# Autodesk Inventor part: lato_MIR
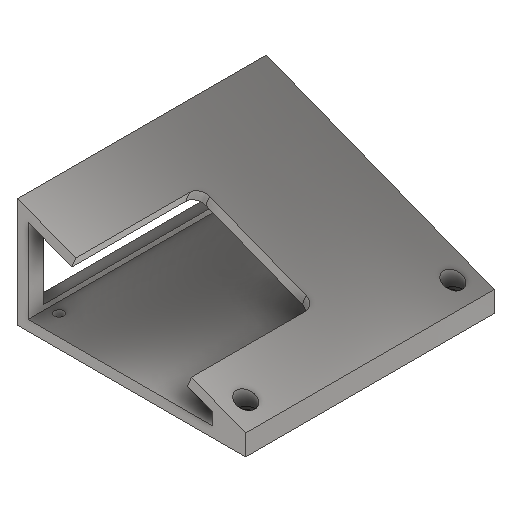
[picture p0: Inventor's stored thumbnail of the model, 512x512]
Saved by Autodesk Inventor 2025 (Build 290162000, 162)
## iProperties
Created: 2025-05
Part Number: lato_MIR
Material: Plastica PET
Document SubType Name: Modeling
Designer: R5800u
Density: 1.541 g/cm^3
Appearance: Policarbonato - Trasparente
Author: R5800u
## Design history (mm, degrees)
derived "lato.ipt"
  sketch "Schizzo1"
    geometry: L1 (0, 0)-(-190, 0) reference; L2 (-190, 0)-(-190, 5) reference; L3 (0, 5)-(-190, 5) reference; L4 (0, 0)-(0, 5) reference; L5 (-300, -48)-(-300, -53) reference; L6 (-300, -48)-(-300, -38) reference; L7 (-300, -38)-(-190, 5) reference; L8 (-190, 5)-(-190, -48) reference; L9 (-190, -48)-(-300, -48) reference; L10 (-195, -2.323)-(-295, -41.414) reference; L11 (-295, -41.414)-(-295, -43) reference; L12 (-295, -43)-(-195, -43) reference; L13 (-195, -43)-(-195, -2.323) reference; L14 (-284, -37.114)-(-284, -43) reference
  sketch "Schizzo2"
    geometry: L1 (0, 53)-(0, 0) reference; L2 (0, 53)-(120, 53) reference; L3 (120, 0)-(120, 53) reference; L4 (0, 0)-(120, 0) reference; L5 (112.5, 45.5)-(7.5, 45.5) reference; L6 (7.5, 45.5)-(7.5, 7.5) reference; L7 (7.5, 7.5)-(112.5, 7.5) reference; L8 (112.5, 7.5)-(112.5, 45.5) reference; 1 further point
  sketch "Schizzo3"
    geometry: L1 (-81.5, -69.5)-(-81.5, -61.5) reference; L2 (-93.5, -69.5)-(-81.5, -69.5) reference; L3 (-93.5, -61.5)-(-93.5, -69.5) reference; L4 (-81.5, -61.5)-(-93.5, -61.5) reference; L5 (-93.5, 61.5)-(-81.5, 61.5) reference; L6 (-81.5, 61.5)-(-81.5, 69.5) reference; L7 (-81.5, 69.5)-(-93.5, 69.5) reference; 1 further point
  sketch "Schizzo4"
    geometry: L1 (-110, -107.9)-(-110, -112.1) reference; L2 (-110, -110)-(-100, -110) reference; L3 (0, -120)-(-110, -120) reference; L4 (-100, -120)-(-100, 0) reference; L5 (0, 0)-(-110, 0) reference; L6 (-100, -60)-(-110, -60) reference; L7 (-110, 0)-(-110, -120) reference; L8 (-100, -10)-(-10, -10) reference; L9 (0, 0)-(0, -120) reference; 6 further points
  sketch "Schizzo7"
    geometry: L1 (-3.641, 120)-(98.81, 120) reference; L2 (88.106, 120)-(28.106, 120) reference; L3 (28.106, 120)-(28.106, 60) reference; L4 (28.106, 60)-(88.106, 60) reference; L5 (88.106, 60)-(88.106, 120) reference; L6 (118.106, 0)-(118.106, 120) reference; 1 further point
  node "Piano di lavoro1"
feature "Solido1::lato.ipt"
tag "Lavorazione contrassegno1"
sketch "Schizzo6"
  geometry: C1 r 2.25 at (-95, 110) reference; C2 r 2.25 at (-95, 10) reference; 1 further point
node "Solido1"
